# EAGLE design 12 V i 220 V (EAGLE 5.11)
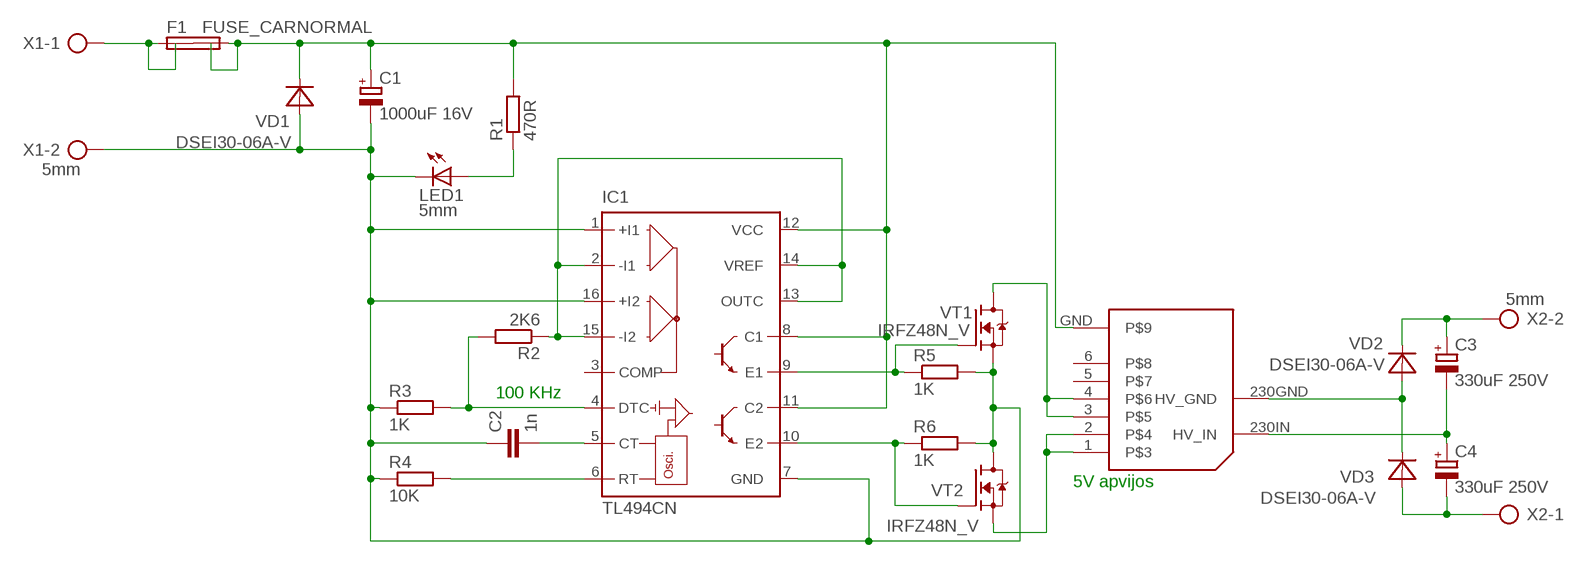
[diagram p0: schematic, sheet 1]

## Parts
C1  1000uF 16V  CPOL-EUE3.5-10  [E3,5-10]
C2  1n  C-EU050-030X075  [C050-030X075]
C3  330uF 250V  CPOL-EUE10-25  [EB25D]
C4  330uF 250V  CPOL-EUE10-25  [EB25D]
F1  FUSE_CARNORMAL  [BLADE_FUSE_NORMAL]
IC1  TL494CN  [DIL16]
LED1  5mm  LED5MM  [LED5MM]
R1  470R  R-EU_0207/5V  [0207/5V]
R2  2K6  R-EU_0207/5V  [0207/5V]
R3  1K  R-EU_0207/5V  [0207/5V]
R4  10K  R-EU_0207/5V  [0207/5V]
R5  1K  R-EU_0207/5V  [0207/5V]
R6  1K  R-EU_0207/5V  [0207/5V]
TR1  ATX_TR_1  [ATX1]
VD1  DSEI30-06A-V  [TO247-V]
VD2  DSEI30-06A-V  [TO247-V]
VD3  DSEI30-06A-V  [TO247-V]
VT1  IRFZ48N_V  [IRFZ48N_TO220V]
VT2  IRFZ48N_V  [IRFZ48N_TO220V]
X1  5mm  AK500/2  [AK500/2]
X2  5mm  AK500/2  [AK500/2]

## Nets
GND: C1.- C2.1 IC1.1(+I1) IC1.7(GND) IC1.16(+I2) LED1.K(C) R3.1 R4.1 R5.2 R6.2 VD1.ANODE(A) VT1.S VT2.D X1.2
N$1: F1.1A F1.1B X1.1
N$3: LED1.A R1.1
N$4: IC1.2(-I1) IC1.13(OUTC) IC1.14(VREF) IC1.15(-I2) R2.1
N$5: IC1.4(DTC) R2.2 R3.2
N$6: C2.2 IC1.5(CT)
N$7: IC1.6(RT) R4.2
N$10: IC1.9(E1) R5.1 VT1.G
N$11: IC1.10(E2) R6.1 VT2.G
N$12: TR1.1 TR1.2 VT2.S
N$13: TR1.3 TR1.4 VT1.D
N$14: TR1.230GND(HV_GND) VD2.ANODE(A) VD3.CATHODE(C)
N$15: C3.- C4.+ TR1.230IN(HV_IN)
N$16: C3.+ VD2.CATHODE(C) X2.2
N$17: C4.- VD3.ANODE(A) X2.1
VCC: C1.+ F1.2A F1.2B IC1.8(C1) IC1.11(C2) IC1.12(VCC) R1.2 TR1.GND VD1.CATHODE(C)
Unconnected: IC1.3(COMP) TR1.5 TR1.6

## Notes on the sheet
- 100 KHz
- 5V apvijos

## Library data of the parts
C1 C3 C4 = rcl:CPOL-EU: POLARIZED CAPACITOR, European symbol
C2 = rcl:C-EU: CAPACITOR, European symbol
F1 = saugikliai:FUSE_CAR: Car fuse Standartinis masininis saugiklis Kaladele su keturiais kontaktais
IC1 = linear:TL494*: SWITCHMODE Pulse Width Modulation Control Circuit NCV494B http://onsemi.com tl494-d.pdf
LED1 = led:LED: LED
R1-R6 = resistor:R-EU_: RESISTOR, European symbol
TR1 = ATX_transformer:ATX_TR_1
VD1-VD3 = diode:DSEI30: DSEI30 - Fast Recovery Epitaxial Diode (FRED) A
VT1 VT2 = tranzistoriai:IRFZ48N_: IRFZ48N 1 - G 2 - D 3 - S 4 - D (korpusas) Description Advanced HEXFET® Power MOSFETs from International Rectifier utilize advanced processing techniques to achieve extremely low on-resistance per silicon area. This benefit, combined with the fast switching speed and ruggedized device design that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
X1 X2 = con-ptr500:AK500/2: CONNECTOR; OC_FARNELL: unknown; OC_NEWARK: unknown

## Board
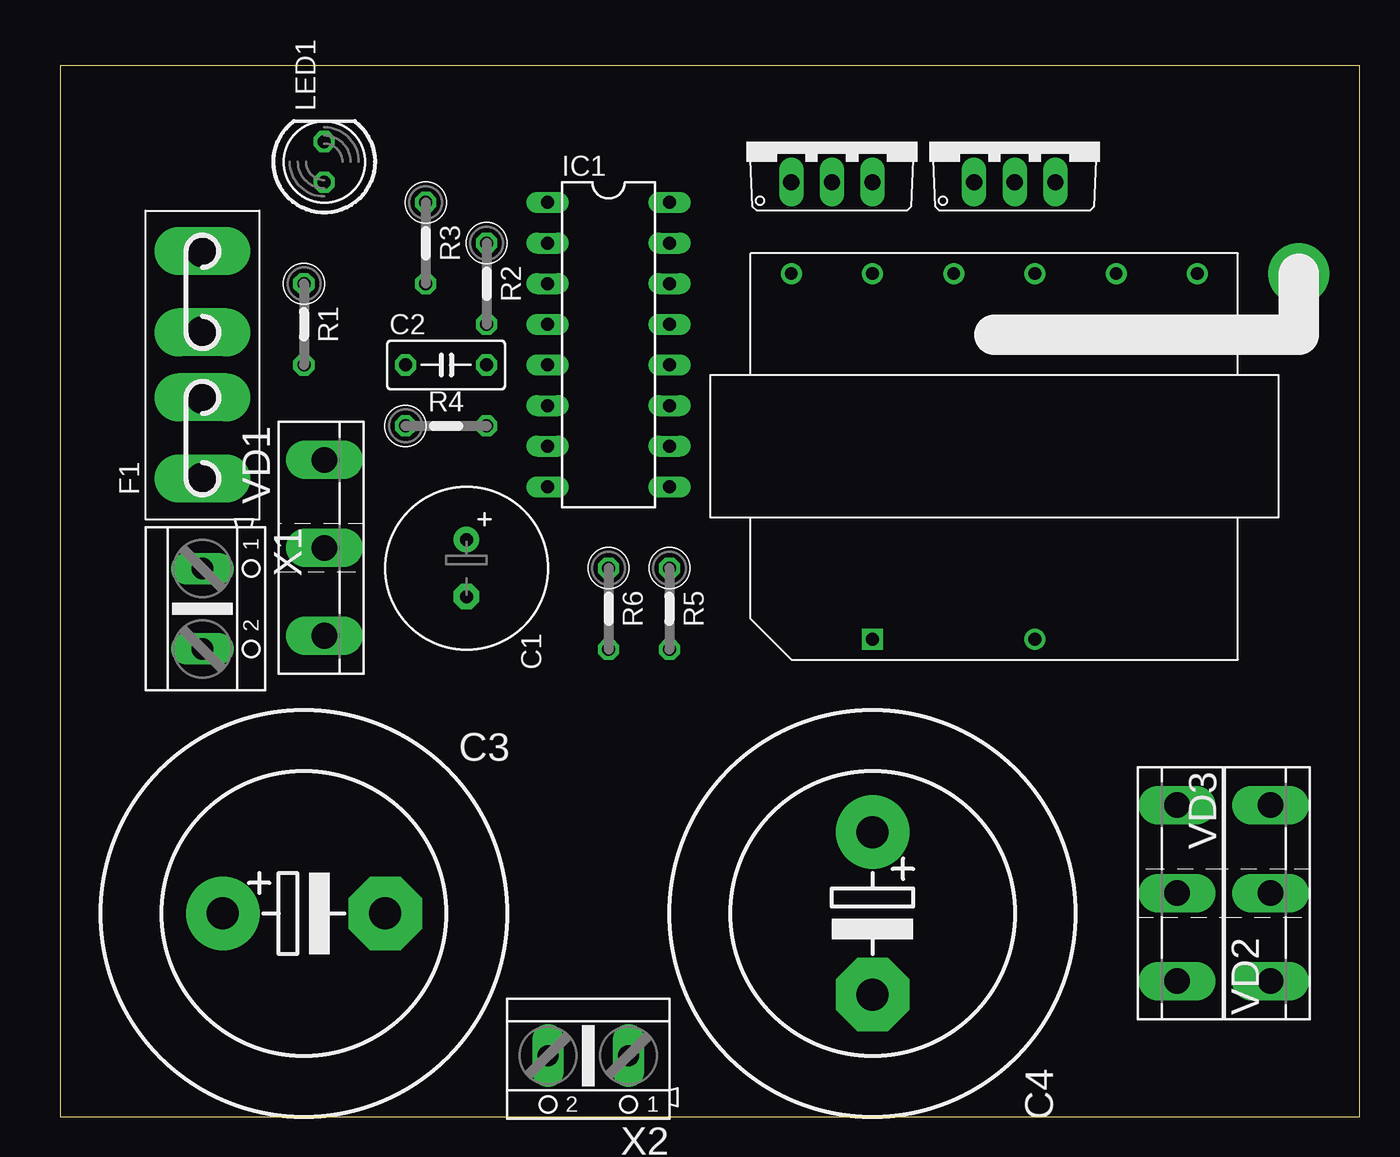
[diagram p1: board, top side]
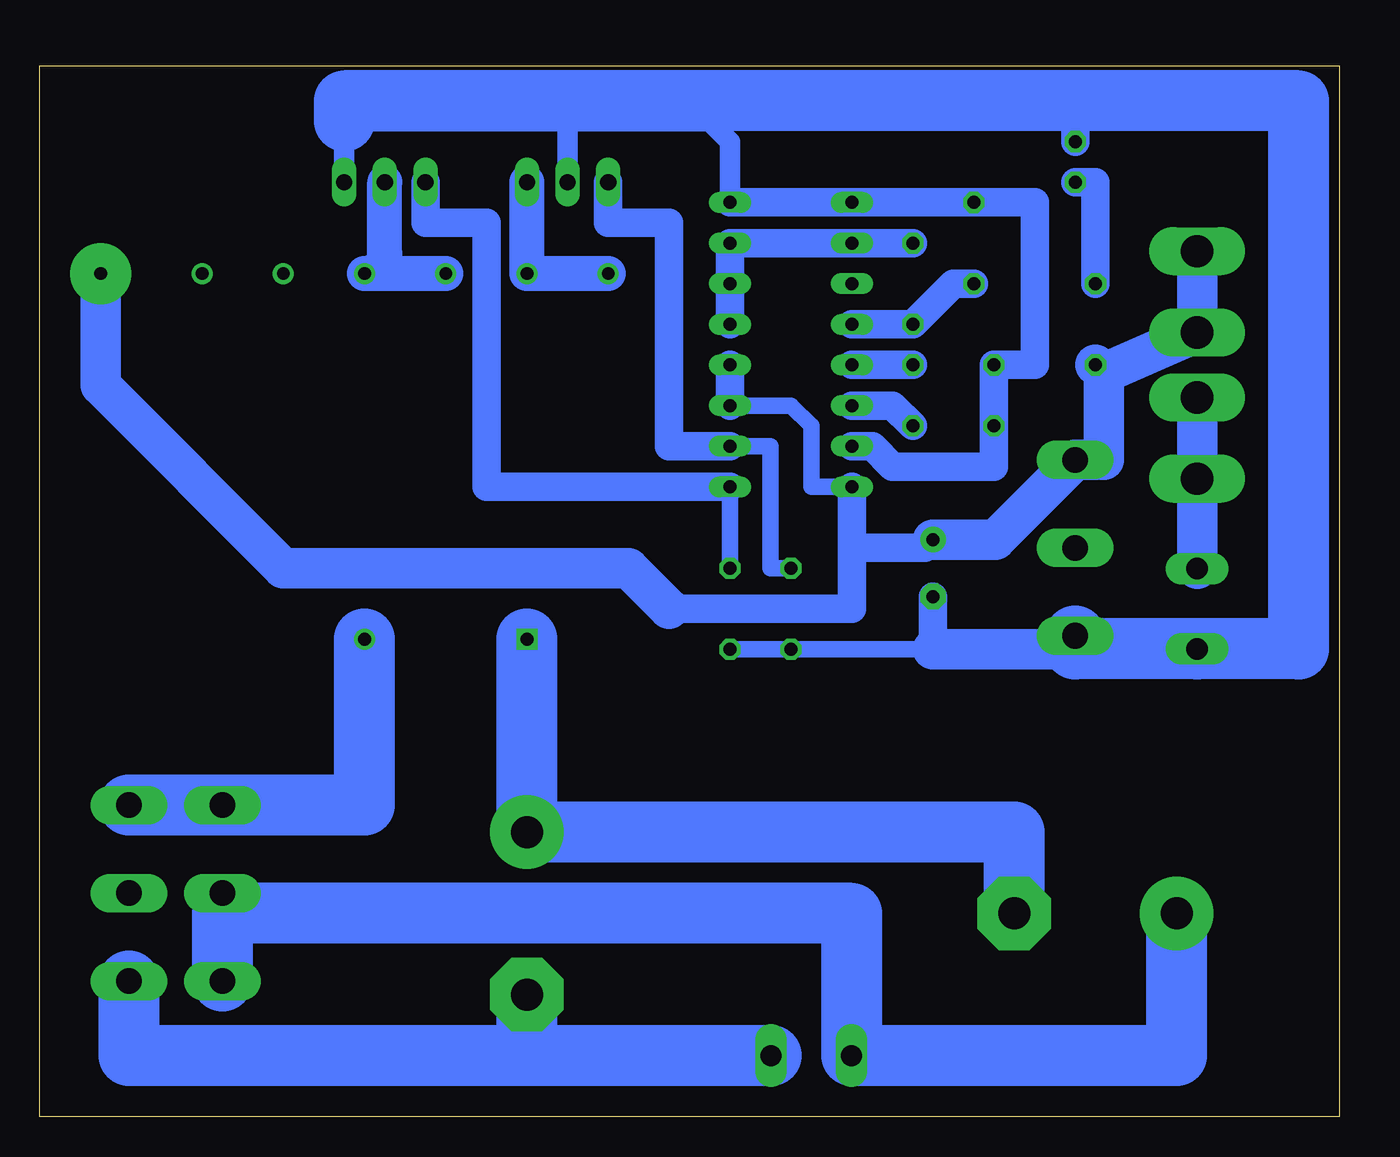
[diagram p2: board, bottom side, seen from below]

Size 81.26 x 65.71 mm. Coordinates in mm from the lower left corner, seen from the top.
Outline: 0,0 81.26,0 81.26,65.71 0,65.71 0,0
Copper layers (1*16): Top 0.035mm / dielectric 1.5mm / Bottom 0.035mm
Design rules "default": minimum track width 10mil, minimum drill 24mil, track to track 8mil, track to pad 8mil, pad to pad 8mil, via to via 8mil, smd to smd 8mil, copper to edge 40mil, drill to drill 8mil, minimum pad ring 10mil, minimum via ring 8mil, stop-mask expansion 4mil, vias tented up to drill 0mil, thermal gap 10mil

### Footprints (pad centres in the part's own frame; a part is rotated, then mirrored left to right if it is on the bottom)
E3,5-10 = drill 0.813 pad 1.6 round: + -1.778,0 | drill 0.813 pad 1.6 octagon: - 1.778,0
C050-030X075 = drill 0.813 octagon: 1 -2.54,0; 2 2.54,0
EB25D = drill 2.007 pad 4.597 round: + -5.08,0 | drill 2.007 pad 4.597 octagon: - 5.08,0
BLADE_FUSE_NORMAL = drill 2.007 long: 1A -7.112,0; 1B -2.032,0; 2A 2.032,0; 2B 7.112,0
DIL16 = drill 0.813 long: 1 -8.89,-3.81; 2 -6.35,-3.81; 3 -3.81,-3.81; 4 -1.27,-3.81; 5 1.27,-3.81; 6 3.81,-3.81; 7 6.35,-3.81; 8 8.89,-3.81; 9 8.89,3.81; 10 6.35,3.81; 11 3.81,3.81; 12 1.27,3.81; 13 -1.27,3.81; 14 -3.81,3.81; 15 -6.35,3.81; 16 -8.89,3.81
LED5MM = drill 0.813 octagon: A -1.27,0; K 1.27,0
0207/5V = drill 0.813 octagon: 1 -2.54,0; 2 2.54,0
ATX1 = drill 0.8 round: 1 10.795,12.7; 2 10.795,7.62; 3 10.795,2.54; 4 10.795,-2.54; 5 10.795,-7.62; 6 10.795,-12.7; 230GND -12.065,-2.54 | drill 0.8 square: 230IN -12.065,7.62 | drill 0.8 pad 3.81 round: GND 10.795,-19.05
TO247-V = drill 1.6 long: ANODE 5.5,0; CATHODE -5.5,0; NC 0,0
IRFZ48N_TO220V = drill 1.016 long: D 0,0; G -2.54,0; S 2.54,0
AK500/2 = drill 1.321 long: 1 -2.515,0; 2 2.515,0

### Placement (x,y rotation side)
C1  25.4,34.29 270 top
C2  24.13,46.99 0 top
C3  15.24,12.7 0 top
C4  50.8,12.7 270 top
F1  8.89,46.99 90 top
IC1  34.29,48.26 270 top
LED1  16.51,59.69 90 top
R1  15.24,49.53 270 top
R2  26.67,52.07 270 top
R3  22.86,54.61 270 top
R4  24.13,43.18 0 top
R5  38.1,31.75 270 top
R6  34.29,31.75 270 top
TR1  58.42,41.91 90 top
VD1  16.51,35.56 270 top
VD2  69.85,13.97 90 top
VD3  75.69,13.97 270 top
VT1  59.69,58.42 0 top
VT2  48.26,58.42 0 top
X1  8.89,31.75 270 top
X2  33.02,3.81 180 top

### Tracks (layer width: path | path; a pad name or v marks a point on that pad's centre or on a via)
GND
  Bottom 1.016: R5.2 R6.2 25.4,29.21
  Bottom 1.27: IC1.16 38.1,60.96 39.37,62.23 48.26,62.23 | 48.26,62.23 VT2.D | VT1.S 62.23,62.23 48.26,62.23
  Bottom 1.778: 25.4,29.21 C1.- | IC1.16 IC1.1 R3.1 19.05,57.15 19.05,46.99 C2.1 R4.1 21.59,40.64 27.94,40.64 29.21,41.91 IC1.7 | 16.51,63.5 LED1.K
  Bottom 2.54: VD1.ANODE 17.36,29.21 25.4,29.21
  Bottom 3.81: 62.23,62.23 62.23,63.5 16.51,63.5 2.54,63.5 2.54,29.23 X1.2 16.51,29.23 VD1.ANODE
N$1
  Bottom 2.54: X1.1 F1.1A F1.1B
N$3
  Bottom 1.778: LED1.A 15.24,58.42 R1.1
N$4
  Bottom 1.778: IC1.13 IC1.14 IC1.15 IC1.2 R2.1
N$5
  Bottom 1.778: R3.2 24.13,52.07 R2.2 IC1.4
N$6
  Bottom 1.778: C2.2 IC1.5
N$7
  Bottom 1.778: R4.2 27.94,44.45 IC1.6
N$10
  Bottom 1.016: R5.1 IC1.9
  Bottom 1.778: IC1.9 53.34,39.37 53.34,55.88 57.15,55.88 VT1.G
N$11
  Bottom 1.016: R6.1 35.56,34.29 35.56,36.83 35.56,41.91 IC1.10
  Bottom 1.778: IC1.10 41.91,41.91 41.91,55.88 45.72,55.88 VT2.G
N$12
  Bottom 2.184: VT2.S TR1.2 TR1.1
N$13
  Bottom 2.184: TR1.3 TR1.4 arc-90 59.69,53.98 VT1.D
N$14
  Bottom 3.81: TR1.230GND 60.96,19.47 VD2.ANODE VD3.CATHODE
N$15
  Bottom 3.81: TR1.230IN C4.+ 20.32,17.78 C3.-
N$16
  Bottom 3.81: VD2.CATHODE 69.85,12.7 30.48,12.7 30.48,3.81 X2.2 10.16,3.81 C3.+
N$17
  Bottom 3.81: VD3.ANODE 75.69,3.81 50.8,3.81 | X2.1 50.8,3.81 | 50.8,3.81 C4.-
VCC
  Bottom 1.016: IC1.11 34.29,44.45 33.02,43.18 33.02,39.37 IC1.8
  Bottom 1.778: IC1.11 IC1.12 | 30.48,35.56 IC1.8 | 30.48,35.56 25.91,35.56 C1.+ | 41.91,31.75 30.48,31.75 30.48,35.56
  Bottom 2.54: F1.2B F1.2A 14.73,46.48 | 14.73,46.48 R1.2 | 14.73,46.48 14.73,41.06 VD1.CATHODE 21.5,36.07 C1.+ | TR1.GND 77.47,45.72 66.04,34.29 44.45,34.29 41.91,31.75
